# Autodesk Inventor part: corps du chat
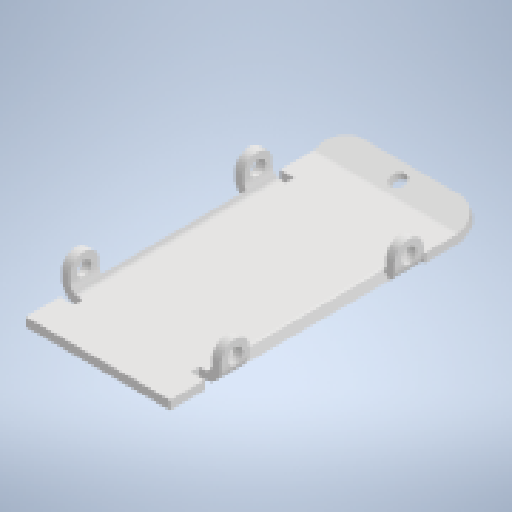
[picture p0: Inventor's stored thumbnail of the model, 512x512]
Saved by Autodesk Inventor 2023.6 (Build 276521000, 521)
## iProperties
Created: 2026-01
Part Number: corps du chat
Material: Générique
Document SubType Name: Sheet Metal
Designer: mel
Density: 1 g/cm^3
Flat Pattern Width: 7 cm
Flat Pattern Length: 10.9392 cm
Flat Pattern Area: 76.5744 cm^2
Sheet Metal Rule: Par défaut_mm
Sheet Metal Width: 70,000 mm
Sheet Metal Length: 109,392 mm
Sheet Metal Area: 7657,443 mm^2
Appearance: Terre battue - Brun foncé
Author: mel
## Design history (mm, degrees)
node "Face1"
  sketch "Esquisse1"
    geometry: L1 (0, 0)-(50, 0); L2 (50, -100)-(0, -100); L3 (50, -15)-(55, -15); L4 (55, -25)-(50, -25); L5 (50, 0)-(50, -15); L6 (25, 0)-(25, -100); L7 (0, -50)-(50, -50); L8 (50, -85)-(55, -85); L9 (55, -75)-(50, -75); L10 (0, -15)-(-5, -15); L11 (-5, -25)-(0, -25); L12 (-5, -75)-(0, -75); L13 (0, -85)-(-5, -85); L14 (0, -15)-(0, 0); L15 (0, -100)-(0, -85); L16 (0, -75)-(0, -25); L17 (50, -25)-(50, -75); L18 (50, -85)-(50, -100); C1 r 2.5 at (55, -20); C2 r 2.5 at (55, -80); C3 r 2.5 at (-5, -20); C4 r 2.5 at (-5, -80); A1 r 5 centre (55, -20) between (55, -25) and (55, -15); A2 r 5 centre (55, -80) between (55, -85) and (55, -75); A3 r 5 centre (-5, -20) between (-5, -15) and (-5, -25); A4 r 5 centre (-5, -80) between (-5, -75) and (-5, -85)
    constraints: 36 end point, 15 symmetric about line, 11 parallel, 8 centre point, 8 point on circle, 5 perpendicular, 4 coincident, 4 midpoint, 2 horizontal, 3 other
    dimensions: "d1" = 100 distance between parallel lines of L2 L1; "d2" = 5 distance of L4.start L4.end; "d3" = 10 distance of L3.end L4.start; "d4" = 5 diameter of C1; "d5" = 5 diameter of C2; "d6" = 5 diameter of C3; "d7" = 5 diameter of C4
sketch "Esquisse2"
  geometry: L1 (-50, 25)-(-50, 75) reference; L2 (-50, 15)-(-50, 25); L3 (-50, 25)-(-50, 85); L4 (0, 15)-(0, 0) reference; L5 (0, 15)-(0, 85)
  constraints: 6 end point, 2 vertical, 1 point on line
feature "Pliage1" sketch "Esquisse2" dims "d8" = 3 (= Epaisseur), "d9" = 3 (= LargeurGrugeage), "d10" = 1.5 (= ProfondeurGrugeage), "d11" = 6 (= RestesMinimum), "d12" = 3 (= Rayondetransition), "d13" = 90 deg, "d14" = 3 (= RayonPli), "SeamGap" = 0.01
sketch "Esquisse3"
  geometry: L1 (-50, 15)-(-55, 15) reference; L2 (-50, 15)-(-50, 85); 1 further point
  constraints: 2 end point, 1 vertical
feature "Pliage2" sketch "Esquisse3" dims "d8" = 3 (= Epaisseur), "d15" = 3 (= LargeurGrugeage), "d16" = 1.5 (= ProfondeurGrugeage), "d17" = 6 (= RestesMinimum), "d18" = 3 (= Rayondetransition), "d19" = 90 deg, "d20" = 3 (= RayonPli), "SeamGap" = 0.01
node "Bord tombé1"
sketch "Esquisse6"
  geometry: L1 (50, 8.942)-(50, 0) reference; L2 (0, 8.942)-(0, 0) reference; L3 (0, 0)-(50, 0) reference; 2 further points
  dimensions: "d43" = 25 distance from line of point (25, 5) L1; "d44" = 25 distance from line of point (25, 5) L2 (derived); "d45" = 5 distance from line of point (25, 5) L3
hole "Perçage1" sketch "Esquisse6" at (25, 5) diameter "d46" = 5; stored, may be unused: countersink angle "d50" = 90 deg, drill point angle "d52" = 118 deg; dims "d47" = 6, "d48" = 4, "d49" = 2, "d51" = 3 (= Epaisseur)
fillet "Congé3" dims "d53" = 8
node "Solide1"
feature "Plaque1" dims "d8" = 3 (= Epaisseur)
sketch "Esquisse4"
  geometry: L1 through (25, 0) direction (-1, 0); L2 through (0, -5) direction (0, -1); L3 (0, -10)-(50, -10); L4 (50, -10)-(50, 0)
  constraints: 6 end point, 1 horizontal, 1 perpendicular, 1 vertical
feature "Plaque2" dims "d8" = 3 (= Epaisseur), "d21" = 3 (= LargeurGrugeage), "d22" = 1.5 (= ProfondeurGrugeage), "d23" = 6 (= RestesMinimum), "d24" = 3 (= Rayondetransition), "d25" = 10, "d26" = -20 deg, "d27" = 3 (= RayonPli), "d28" = 12 (= TailleGrugeage), "d29" = 3 (= TailleJeu), "d30" = 3 (= TailleRayonJacobi), "SeamGap" = 0.01
feature "Pli1" dims "d8" = 3 (= Epaisseur), "d21" = 3 (= LargeurGrugeage), "d22" = 1.5 (= ProfondeurGrugeage), "d23" = 6 (= RestesMinimum), "d24" = 3 (= Rayondetransition), "d25" = 10, "d26" = -20 deg, "d27" = 3 (= RayonPli), "SeamGap" = 0.01
feature "Coin1" dims "d25" = 10, "d26" = -20 deg, "d28" = 12 (= TailleGrugeage), "d29" = 3 (= TailleJeu), "d30" = 3 (= TailleRayonJacobi)
feature "Définition1"
other parameters: "Epaisseur" = 3 (derived), "RayonPli" = 3 (= Epaisseur), "LargeurGrugeage" = 3 (= Epaisseur), "ProfondeurGrugeage" = 1.5 (= 0.5 x Epaisseur), "TailleGrugeage" = 12 (= 4 x Epaisseur), "RestesMinimum" = 6 (= 2 x Epaisseur), "Rayondetransition" = 3 (= RayonPli), "TailleRayonJacobi" = 3 (= RayonPli), "TailleJeu" = 3 (= Epaisseur), "Epaisseur" = 3, "LargeurGrugeage" = 3, "ProfondeurGrugeage" = 1.5, "RayonPli" = 3, "Rayondetransition" = 3, "RestesMinimum" = 6, "TailleGrugeage" = 12, "TailleJeu" = 3, "TailleRayonJacobi" = 3
